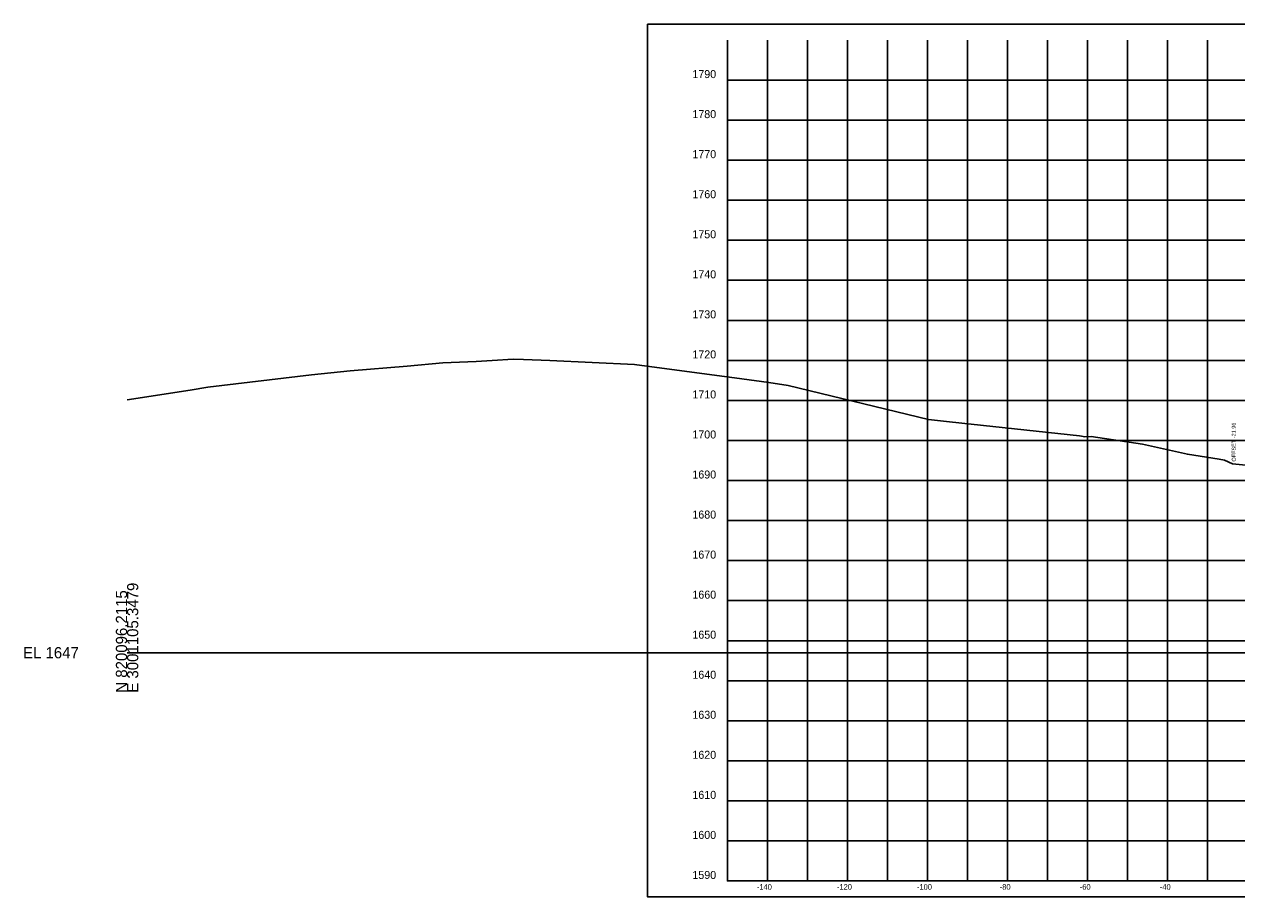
# Model space of a CAD drawing. Extents: x -26 to 603, y -61 to 1770.
# Drawn here: x -25.7 to 277.3, y -60.9 to 156.9 of the extents above; entities that cross this region are included whole.
import ezdxf

# ---------------------------------------------------------------- set-up
doc = ezdxf.new("R2010")
doc.units = 0
for name, color, linetype in [('DESIGN - SHEET - Corner Text', 7, 'Continuous'), ('DESIGN - SHEET - Light Grid', 7, 'Continuous'), ('DESIGN - SHEET - Linework', 7, 'Continuous'), ('DESIGN - SHEET - Plot Shape', 7, 'Continuous'), ('DESIGN - TYPICAL - Slope Tie Text', 7, 'Continuous'), ('SURVEY - GROUND - Top of Ground', 7, 'Continuous')]:
    doc.layers.add(name, color=color, linetype=linetype)

msp = doc.modelspace()

# ---------------------------------------------------------------- linework, layer by layer
at = {"layer": 'DESIGN - SHEET - Light Grid'}
msp.add_line((0, 0), (300, 0), dxfattribs=at)
at = {"layer": 'DESIGN - SHEET - Linework'}
for p, q in [((160, -57), (160, 153)), ((170, -57), (170, 153)), ((180, -57), (180, 153)), ((190, -57), (190, 153)), ((200, -57), (200, 153)), ((210, -57), (210, 153)), ((220, -57), (220, 153)), ((230, -57), (230, 153)), ((240, -57), (240, 153)), ((250, -57), (250, 153)), ((260, -57), (260, 153)), ((270, -57), (270, 153)), ((150, 143), (450, 143)), ((150, 133), (450, 133)), ((150, 123), (450, 123)), ((150, 113), (450, 113)), ((150, 103), (450, 103)), ((150, 93), (450, 93)), ((150, 83), (450, 83)), ((150, 73), (450, 73)), ((150, 63), (450, 63)), ((150, 53), (450, 53)), ((150, 43), (450, 43)), ((150, 33), (450, 33)), ((150, 23), (450, 23)), ((150, 13), (450, 13)), ((150, 3), (450, 3)), ((150, -7), (450, -7)), ((150, -17), (450, -17)), ((150, -27), (450, -27)), ((150, -37), (450, -37)), ((150, -47), (450, -47))]:
    msp.add_line(p, q, dxfattribs=at)
msp.add_lwpolyline([(150, 153), (150, -57), (450, -57), (450, 153)], dxfattribs=at)
at = {"layer": 'DESIGN - SHEET - Plot Shape'}
msp.add_lwpolyline([(130, 156.94), (470, 156.94), (470, -60.94), (130, -60.94)], close=True, dxfattribs=at)
at = {"layer": 'SURVEY - GROUND - Top of Ground'}
msp.add_lwpolyline([(0, 63.12), (15.78, 65.58), (20.22, 66.28), (46.07, 69.37), (55.73, 70.39), (70, 71.54), (78.93, 72.41), (87.25, 72.69), (91.25, 72.97), (96.44, 73.27), (99.02, 73.26), (105.6, 72.97), (126.76, 71.95), (153.61, 68.43), (160.39, 67.46), (165.16, 66.71), (200.27, 58.28), (205.52, 57.69), (237.95, 54.13), (238.51, 54.04), (239.29, 53.92), (240.88, 53.99), (253.71, 52.09), (264.97, 49.54), (272.92, 48.33), (274.21, 48.09), (276.24, 47.15), (282.06, 46.58)], dxfattribs=at)

# ---------------------------------------------------------------- texts
at = {"layer": 'DESIGN - SHEET - Corner Text'}
for s, height, p in [('1790', 2, (141.25, 143.5)), ('1780', 2, (141.25, 133.5)), ('1770', 2, (141.25, 123.5)), ('1760', 2, (141.25, 113.5)), ('1750', 2, (141.25, 103.5)), ('1740', 2, (141.25, 93.5)), ('1730', 2, (141.25, 83.5)), ('1720', 2, (141.25, 73.5)), ('1710', 2, (141.25, 63.5)), ('1700', 2, (141.25, 53.5)), ('1690', 2, (141.25, 43.5)), ('1680', 2, (141.25, 33.5)), ('1670', 2, (141.25, 23.5)), ('1660', 2, (141.25, 13.5)), ('1650', 2, (141.25, 3.5)), ('1640', 2, (141.25, -6.5)), ('1630', 2, (141.25, -16.5)), ('1620', 2, (141.25, -26.5)), ('1610', 2, (141.25, -36.5)), ('1600', 2, (141.25, -46.5)), ('1590', 2, (141.25, -56.5)), ('-140', 1.4, (157.37, -59.2)), ('-120', 1.4, (177.37, -59.2)), ('-100', 1.4, (197.37, -59.2)), ('-80', 1.4, (218.06, -59.2)), ('-60', 1.4, (238.06, -59.2)), ('-40', 1.4, (258.06, -59.2))]:
    msp.add_text(s, height=height, dxfattribs=at).set_placement(p)
at = {"layer": 'DESIGN - SHEET - Light Grid'}
for s, p in [('N 820096.2115', (0, -10)), ('E 3001105.3479', (2.8, -10))]:
    msp.add_text(s, height=2.8, rotation=90, dxfattribs=at).set_placement(p)
msp.add_text('EL 1647', height=2.8, dxfattribs=at).set_placement((-26, -1.4))
at = {"layer": 'DESIGN - TYPICAL - Slope Tie Text'}
msp.add_text('OFFSET -21.96', height=1, rotation=90, dxfattribs=at).set_placement((277.04, 47.72))

doc.saveas('drawing.dxf')
